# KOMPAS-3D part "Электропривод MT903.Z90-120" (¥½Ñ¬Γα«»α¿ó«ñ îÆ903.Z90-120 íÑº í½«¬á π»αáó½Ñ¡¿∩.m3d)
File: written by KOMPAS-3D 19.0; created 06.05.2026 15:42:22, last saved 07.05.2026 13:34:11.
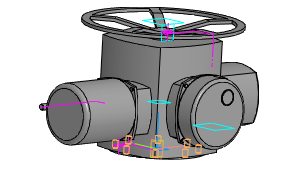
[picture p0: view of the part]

Document properties: Автор: Энергия; Полное имя файла: Z:\3.Личные\kachalov\3d для проектировщиков\2.2 Тип 47GVA, 47GVA.Z\Привод\Электропривод МТ903.Z90-120 без блока управления.m3d

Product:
- Part/product: Электропривод MT903.Z90-120
    Масса: 369.82

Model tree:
1. Эскиз:1
2. Элемент выдавливания:1
     Расстояние 1 = 344
3. Эскиз:2
4. Элемент выдавливания:2
     Расстояние 1 = 205
5. Эскиз:3  (with: Элемент выдавливания:2)
6. Элемент выдавливания:3
     Расстояние 1 = 10
7. Эскиз:4  (with: Элемент выдавливания:3)
8. Элемент выдавливания:4
     Расстояние 1 = 205
9. Скругление:1  (with: Элемент выдавливания:4)
     Радиус = 15
10. Эскиз:5
11. Элемент выдавливания:5
     Расстояние 1 = 190
12. Эскиз:6  (with: Элемент выдавливания:5)
13. Элемент выдавливания:6
     Расстояние 1 = 10
14. Эскиз:7  (with: Элемент выдавливания:6)
15. Элемент выдавливания:7
     Расстояние 1 = 68
16. Скругление:2  (with: Элемент выдавливания:7)
     Радиус = 10
17. Эскиз:8
18. Элемент выдавливания:8
     Расстояние 1 = 330
19. Скругление:3  (with: Элемент выдавливания:8)
     Радиус = 5
20. Касательная плоскость:1  (with: Элемент выдавливания:8)
21. Эскиз:10
22. Элемент выдавливания:9
     Расстояние 1 = 5
23. Эскиз:11  (with: Элемент выдавливания:9)
24. Отверстие:1  (with: Элемент выдавливания:9)  (labels: M16)
     Глубина выреза = 30; Диаметр отверстия = 13.8349; Угол конуса дна = 118; Расстояние 1 = -127
25. M16  (with: Элемент выдавливания:9)  (labels: M16; cil0_24705-2004 coarse)
     Длина резьбы = 24; Шаг резьбы = 2; Номинальный диаметр резьбы = 16
26. Массив по концентрической сетке:1  (with: Отверстие:1, Эскиз:11)  (labels: M16)  (2 pattern instances)
27. M10  (with: Отверстие:1, Элемент выдавливания:9, Эскиз:11)  (labels: M16; cil0_24705-2004 coarse)  (1 pattern instances)
     Длина резьбы = 24; Шаг резьбы = 2; Номинальный диаметр резьбы = 16
28. Отверстие:1  (with: Эскиз:11)  (labels: M16)
29. Отверстие:1  (with: Эскиз:11)  (labels: M16)
30. Отверстие:1  (with: Эскиз:11)  (labels: M16)
31. Отверстие:1  (with: Эскиз:11)  (labels: M16)
32. Отверстие:1  (with: Эскиз:11)  (labels: M16)
33. Эскиз:12  (with: Элемент выдавливания:9)
34. Элемент выдавливания:10
     Расстояние 1 = 5
35. Эскиз:13  (with: Элемент выдавливания:10)
36. Элемент выдавливания:11
     Расстояние 2 = 50
37. Эскиз:14
38. Элемент выдавливания:14  (with: Элемент выдавливания:8)
     Расстояние 1 = 15; Расстояние 2 = 10
39. Эскиз:15  (with: Элемент выдавливания:1)
40. Элемент выдавливания:15
     Расстояние 1 = 15
41. Эскиз:16  (with: Элемент выдавливания:15)
42. Смещенная плоскость:1  (with: Элемент выдавливания:15)
     Расстояние = 35
43. Эскиз:17  (with: Элемент выдавливания:15)
44. Элемент выдавливания:16
     Расстояние 1 = 10
45. Элемент выдавливания:17
     Расстояние 1 = 10
46. Эскиз:20  (with: Элемент выдавливания:16, Элемент выдавливания:17)
47. Перпендикулярная плоскость:1
48. Эскиз:21
49. Элемент по траектории:1
50. Массив по концентрической сетке:5  (with: Элемент по траектории:1, Эскиз:21, Элемент выдавливания:17)  (5 pattern instances)
     Шаг 2 = 360
51. Скругление:5  (with: Элемент выдавливания:14, Элемент выдавливания:7, Элемент выдавливания:4)
     Радиус = 1
52. Эскиз:22  (with: Элемент выдавливания:3, Скругление:5)
53. Элемент выдавливания:18
     Расстояние 1 = 5
54. Скругление:6  (with: Элемент выдавливания:18)
     Радиус = 1
55. Массив по концентрической сетке:3  (with: Элемент выдавливания:18, Эскиз:22, Скругление:6, Элемент выдавливания:4)  (4 pattern instances)
     Шаг 2 = 360
56. Эскиз:23  (with: Элемент выдавливания:6, Скругление:5)
57. Элемент выдавливания:19
     Расстояние 1 = 5
58. Скругление:7  (with: Элемент выдавливания:19)
     Радиус = 1
59. Массив по концентрической сетке:4  (with: Элемент выдавливания:19, Эскиз:23, Скругление:7, Элемент выдавливания:7)  (4 pattern instances)
     Шаг 2 = 360
60. Эскиз:24
61. Элемент выдавливания:20
     Расстояние 1 = 60
62. Смещенная плоскость:2
63. Эскиз:25  (with: Элемент выдавливания:20)
64. Эскиз:26  (with: Элемент выдавливания:20)
65. Элемент по траектории:2
66. Фаска:1  (with: Элемент по траектории:2)
     Угол = 45; Длина 1 = 2; Длина 2 = 2
67. Эскиз:27  (with: Элемент выдавливания:7)
68. Элемент выдавливания:21
     Расстояние 1 = 3
69. Эскиз:28  (with: Элемент выдавливания:21)
70. Элемент выдавливания:22
     Расстояние 2 = 1

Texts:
  Точка начала. Х
  Точка начала. Y
  Точка начала. Z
